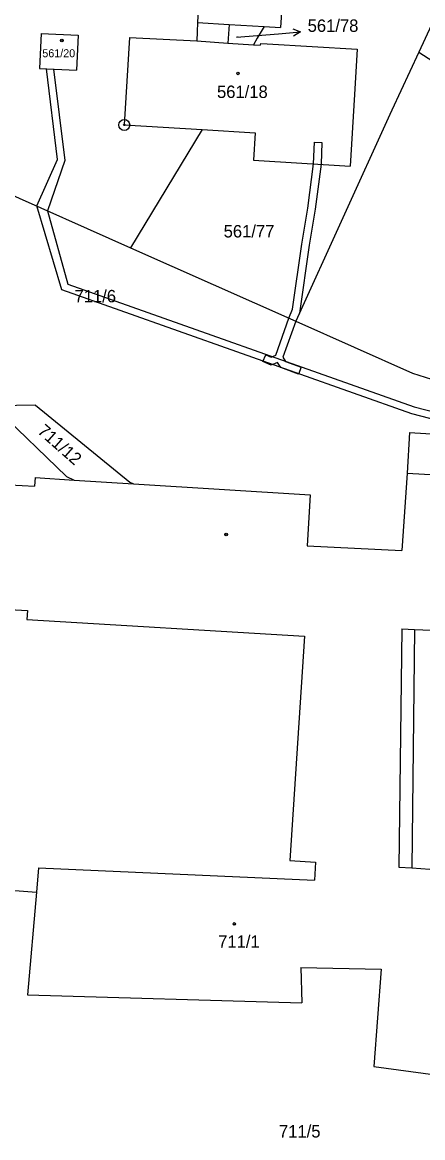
# Model space of a CAD drawing. Extents: x -593183 to -588034, y -1130415 to -1124994.
# Drawn here: x -591341.4 to -591286.6, y -1128786.6 to -1128633.8 of the extents above; entities that cross this region are included whole.
import ezdxf

# ---------------------------------------------------------------- set-up
doc = ezdxf.new("R2010")
doc.units = 0
for name, color, linetype in [('Vrstva 1', 7, 'Continuous'), ('Vrstva 16', 7, 'Continuous'), ('Vrstva 18', 7, 'Continuous'), ('Vrstva 19', 7, 'Continuous'), ('Vrstva 24', 7, 'Continuous'), ('Vrstva 25', 7, 'Continuous'), ('Vrstva 27', 7, 'Continuous'), ('Vrstva 4', 7, 'Continuous')]:
    doc.layers.add(name, color=color, linetype=linetype)

msp = doc.modelspace()

# ---------------------------------------------------------------- linework, layer by layer
at = {"layer": 'Vrstva 1'}
for p, q in [((-591316.54, -1128616.83), (-591317.42, -1128633.78)), ((-591277.3, -1128616.57), (-591287.14, -1128637.85)), ((-591305.81, -1128630.18), (-591306.05, -1128634.46)), ((-591317.42, -1128633.78), (-591317.49, -1128635.08)), ((-591317.42, -1128633.78), (-591313.12, -1128634.04)), ((-591313.12, -1128634.04), (-591313.27, -1128636.63)), ((-591313.12, -1128634.04), (-591308.29, -1128634.33)), ((-591338.87, -1128635.31), (-591339.08, -1128640.11)), ((-591338.87, -1128635.31), (-591333.8, -1128635.53)), ((-591333.8, -1128635.53), (-591334.01, -1128640.34)), ((-591317.49, -1128635.08), (-591317.55, -1128636.28)), ((-591308.29, -1128634.33), (-591309.26, -1128635.95)), ((-591308.29, -1128634.33), (-591306.05, -1128634.46)), ((-591326.76, -1128635.82), (-591327.48, -1128647.83)), ((-591326.76, -1128635.82), (-591317.55, -1128636.28)), ((-591313.27, -1128636.63), (-591309.79, -1128636.83)), ((-591309.26, -1128635.95), (-591309.79, -1128636.83)), ((-591309.79, -1128636.83), (-591308.84, -1128636.88)), ((-591308.82, -1128636.68), (-591308.84, -1128636.88)), ((-591308.82, -1128636.68), (-591307.9, -1128636.73)), ((-591307.9, -1128636.73), (-591295.56, -1128637.43)), ((-591295.56, -1128637.43), (-591295.93, -1128643.63)), ((-591287.14, -1128637.85), (-591290.82, -1128645.8)), ((-591287.14, -1128637.85), (-591269.02, -1128649.56)), ((-591339.08, -1128640.11), (-591334.01, -1128640.34)), ((-591295.93, -1128643.63), (-591296.52, -1128653.46)), ((-591291.1, -1128646.41), (-591303.98, -1128674.7)), ((-591290.82, -1128645.8), (-591291.1, -1128646.41)), ((-591327.48, -1128647.83), (-591316.82, -1128648.47)), ((-591316.82, -1128648.47), (-591326.6, -1128664.64)), ((-591316.82, -1128648.47), (-591309.54, -1128648.9)), ((-591309.54, -1128648.9), (-591309.76, -1128652.67)), ((-591360.14, -1128649.72), (-591326.6, -1128664.64)), ((-591309.76, -1128652.67), (-591296.52, -1128653.46)), ((-591326.6, -1128664.64), (-591303.98, -1128674.7)), ((-591303.98, -1128674.7), (-591287.97, -1128681.82)), ((-591287.97, -1128681.82), (-591284.51, -1128682.92)), ((-591339.64, -1128686.22), (-591345.42, -1128686.34)), ((-591345.42, -1128686.34), (-591335.37, -1128696)), ((-591339.64, -1128686.22), (-591326.73, -1128696.75)), ((-591288.4, -1128689.96), (-591288.73, -1128695.52)), ((-591288.4, -1128689.96), (-591277.67, -1128690.6)), ((-591350.48, -1128696.68), (-591339.77, -1128697.34)), ((-591339.69, -1128696.14), (-591339.77, -1128697.34)), ((-591339.69, -1128696.14), (-591334.33, -1128696.48)), ((-591335.37, -1128696), (-591334.33, -1128696.48)), ((-591334.33, -1128696.48), (-591326.22, -1128696.98)), ((-591326.73, -1128696.75), (-591326.22, -1128696.98)), ((-591288.73, -1128695.52), (-591289.43, -1128706.13)), ((-591326.22, -1128696.98), (-591302.01, -1128698.5)), ((-591302.01, -1128698.5), (-591302.4, -1128705.51)), ((-591302.4, -1128705.51), (-591289.43, -1128706.13)), ((-591351.54, -1128713.75), (-591340.74, -1128714.35)), ((-591340.74, -1128714.35), (-591340.81, -1128715.61)), ((-591340.81, -1128715.61), (-591302.8, -1128717.88)), ((-591302.8, -1128717.88), (-591304.79, -1128748.63)), ((-591287.72, -1128716.96), (-591288.1, -1128749.63)), ((-591287.72, -1128716.96), (-591275.97, -1128717.43)), ((-591304.79, -1128748.63), (-591301.26, -1128748.86)), ((-591339.23, -1128749.63), (-591339.52, -1128752.93)), ((-591339.23, -1128749.63), (-591301.42, -1128751.31)), ((-591301.26, -1128748.86), (-591301.42, -1128751.31)), ((-591288.1, -1128749.63), (-591271.91, -1128750.73)), ((-591342.49, -1128752.73), (-591339.52, -1128752.93)), ((-591339.52, -1128752.93), (-591340.75, -1128767.02)), ((-591303.29, -1128763.26), (-591292.26, -1128763.5)), ((-591303.29, -1128763.26), (-591303.15, -1128768.11)), ((-591292.26, -1128763.5), (-591293.29, -1128776.86)), ((-591340.75, -1128767.02), (-591303.15, -1128768.11)), ((-591293.29, -1128776.86), (-591277.12, -1128779.02))]:
    msp.add_line(p, q, dxfattribs=at)
at = {"layer": 'Vrstva 16'}
msp.add_line((-591312.11, -1128635.79), (-591306.34, -1128635.32), dxfattribs=at)
at = {"layer": 'Vrstva 24'}
for radius in [0.75, 0.0903]:
    msp.add_circle((-591327.48, -1128647.83), radius, dxfattribs=at)
at = {"layer": 'Vrstva 25'}
msp.add_line((-591306.34, -1128635.32), (-591303.35, -1128635.07), dxfattribs=at)
msp.add_lwpolyline([(-591304.39, -1128634.66), (-591303.35, -1128635.07), (-591304.31, -1128635.65)], dxfattribs=at)
for centre, radius in [((-591336.02, -1128636.25), 0.175), ((-591336.02, -1128636.25), 0.15), ((-591311.9, -1128640.76), 0.175), ((-591311.9, -1128640.76), 0.15), ((-591313.51, -1128703.94), 0.175), ((-591313.51, -1128703.94), 0.15), ((-591312.4, -1128757.3), 0.175), ((-591312.4, -1128757.3), 0.15)]:
    msp.add_circle(centre, radius, dxfattribs=at)
at = {"layer": 'Vrstva 27'}
for p, q in [((-591338.15, -1128640.15), (-591337.15, -1128640.2)), ((-591336.64, -1128652.55), (-591338.15, -1128640.15)), ((-591337.15, -1128640.2), (-591335.62, -1128652.71)), ((-591301.53, -1128653.16), (-591301.39, -1128650.18)), ((-591301.39, -1128650.18), (-591300.39, -1128650.24)), ((-591300.39, -1128650.24), (-591300.52, -1128653.22)), ((-591339.45, -1128658.92), (-591336.64, -1128652.55)), ((-591335.62, -1128652.71), (-591338.01, -1128659.57)), ((-591302.31, -1128659.21), (-591301.53, -1128653.16)), ((-591300.52, -1128653.22), (-591301.33, -1128659.37)), ((-591336.01, -1128670.42), (-591339.45, -1128658.92)), ((-591338.01, -1128659.57), (-591335.21, -1128669.64)), ((-591303.14, -1128664.14), (-591302.31, -1128659.21)), ((-591301.33, -1128659.37), (-591302.16, -1128664.28)), ((-591304.42, -1128673.05), (-591303.14, -1128664.14)), ((-591302.16, -1128664.28), (-591303.49, -1128673.62)), ((-591288.07, -1128687.43), (-591336.01, -1128670.42)), ((-591335.21, -1128669.64), (-591287.77, -1128686.47)), ((-591304.91, -1128674.29), (-591304.42, -1128673.05)), ((-591303.49, -1128673.62), (-591303.98, -1128674.7)), ((-591306.73, -1128679.37), (-591304.91, -1128674.29)), ((-591303.98, -1128674.7), (-591305.77, -1128679.66)), ((-591308.47, -1128680.26), (-591308.09, -1128679.34)), ((-591308.09, -1128679.34), (-591307.35, -1128679.65)), ((-591307.35, -1128679.65), (-591306.73, -1128679.37)), ((-591305.77, -1128679.66), (-591305.38, -1128680.22)), ((-591307.33, -1128680.73), (-591308.47, -1128680.26)), ((-591306.49, -1128680.36), (-591307.33, -1128680.73)), ((-591306.02, -1128681.04), (-591306.49, -1128680.36)), ((-591303.62, -1128681.97), (-591306.02, -1128681.04)), ((-591305.38, -1128680.22), (-591303.26, -1128681.03)), ((-591303.26, -1128681.03), (-591303.62, -1128681.97)), ((-591268.91, -1128692.36), (-591288.07, -1128687.43)), ((-591287.77, -1128686.47), (-591268.55, -1128691.42))]:
    msp.add_line(p, q, dxfattribs=at)
at = {"layer": 'Vrstva 4'}
for p, q in [((-591317.55, -1128636.28), (-591313.27, -1128636.63)), ((-591288.73, -1128695.52), (-591278, -1128696.16)), ((-591289.47, -1128716.89), (-591289.88, -1128749.51)), ((-591289.47, -1128716.89), (-591287.72, -1128716.96)), ((-591289.88, -1128749.51), (-591288.1, -1128749.63))]:
    msp.add_line(p, q, dxfattribs=at)

# ---------------------------------------------------------------- texts
at = {"layer": 'Vrstva 16'}
msp.add_text('561/78', height=1.7, dxfattribs=at).set_placement((-591302.35, -1128635.07))
at = {"layer": 'Vrstva 18'}
for s, height, p in [('561/78', 0.1, (-591312.11, -1128635.79)), ('561/77', 1.7, (-591313.86, -1128663.24)), ('711/6', 1.7, (-591334.29, -1128672.13)), ('711/5', 1.7, (-591306.28, -1128786.57))]:
    msp.add_text(s, height=height, dxfattribs=at).set_placement(p)
msp.add_text('711/12', height=1.7, rotation=318.521, dxfattribs=at).set_placement((-591339.47, -1128689.95))
at = {"layer": 'Vrstva 19'}
for s, height, p in [('561/20', 1.1, (-591338.7, -1128638.55)), ('561/18', 1.7, (-591314.77, -1128644.13)), ('711/1', 1.7, (-591314.61, -1128760.57))]:
    msp.add_text(s, height=height, dxfattribs=at).set_placement(p)

doc.saveas('drawing.dxf')
